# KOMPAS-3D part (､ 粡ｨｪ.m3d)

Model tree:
1. Эскиз:2
2. Операция выдавливания:1
     Расстояние 1 = 35; Угол 1 = 4
3. Эскиз:3
4. Вырезать элемент выдавливания:1
     Расстояние 2 = 35; Угол 2 = 1.91; Расстояние 1 = 10
5. Оболочка:2
     Толщина стенки 2 = 1
6. Эскиз:8
7. Вырезать элемент выдавливания:4
     Расстояние 2 = 11.1672; Расстояние 1 = 11.1672
8. Эскиз:10
9. Операция выдавливания:4
     Расстояние 1 = 1; Угол 2 = 1.98
10. Эскиз:16
11. Операция выдавливания:9
     Расстояние 1 = 2; Расстояние 2 = 1; Угол 2 = 4
12. Эскиз:17
13. Операция выдавливания:10
     Расстояние 1 = 15; Расстояние 2 = 15; Угол 2 = 4
14. Эскиз:18
15. Операция выдавливания:11
     Расстояние 1 = 1; Расстояние 2 = 15; Угол 2 = 4
16. Скругление:1
     Радиус = 1
17. Скругление:2
     Радиус = 1
18. Скругление:3
     Радиус = 1
19. Эскиз:19
20. Вырезать элемент выдавливания:5
     Расстояние 1 = 15.9339
21. Эскиз:20
22. Вырезать элемент выдавливания:6
     Расстояние 1 = 17
23. Эскиз:21
24. Вырезать элемент выдавливания:7
     Расстояние 1 = 15
25. Эскиз:22
26. Вырезать элемент выдавливания:8
     Расстояние 1 = 15
